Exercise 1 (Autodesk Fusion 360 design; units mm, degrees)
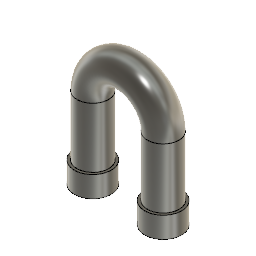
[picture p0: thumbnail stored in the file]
sketch "Sketch1" plane through (0, 0, 0) normal (0, 1, 0) x axis (1, 0, 0)
  line L1 (0, -170) -> (0, 0)
  line L2 (200, 0) -> (200, -170)
  arc A1 centre (100, -170) radius 100 clockwise from (200, -170) to (0, -170)
  point P1 (0, 0)
  point P2 (0, 0)
  point P3 (0, -170)
  coincident P1 P2
  vertical L1
  tangent L1 A1
  tangent A1 L2
  parallel L1 L2
  equal L1 L2
  dimension "d1" distance P2 P3 = 170
  dimension "d2" radius A1 = 100
sketch "Sketch2" plane through (0, 0, 0) normal (0, 0, 1) x axis (1, 0, 0)
  circle C1 centre (0, 0) radius 45
  circle C2 centre (0, 0) radius 35
  point P1 (0, 0)
  point P2 (0, 0)
  point P3 (0, 0)
  coincident P1 P2
  coincident P1 P3
  dimension "d3" diameter C1 = 90
  dimension "d4" diameter C2 = 70
sweep "Sweep1" sketch "Sketch2" TwistAngle 0 TaperAngle 0
sketch "Sketch3" plane through (0, 0, 0) normal (0, 0, -1) x axis (1, 0, 0)
  circle C1 centre (0, 0) radius 35
  circle C2 centre (0, 0) radius 45
  circle C3 centre (0, 0) radius 52.5
  circle C4 centre (200, 0) radius 52.5
  circle C5 centre (200, 0) radius 35
  point P1 (0, 0)
  point P3 (0, 0)
  coincident P1 P3
  concentric C4 C5
  equal C3 C4
  dimension "d11" diameter C3 = 105
extrude "Extrude1" add sketch "Sketch3" along normal blind 60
